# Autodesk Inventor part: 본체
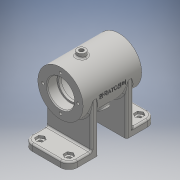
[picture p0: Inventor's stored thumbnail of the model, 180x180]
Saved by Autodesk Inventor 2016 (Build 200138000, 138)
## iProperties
Created: 2017-02
Part Number: 본체
Material: 일반
Document SubType Name: Modeling
Designer: USER
Density: 1 g/cm^3
Appearance: 기본값
Author: USER
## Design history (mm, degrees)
sketch "스케치1"
  geometry: L1 (0, 0)-(54, 0); L2 (54, 0)-(54, -35); L3 (54, -35)-(0, -35); L4 (0, -35)-(0, 0); L5 (0, -69)-(54, -69); L6 (54, -69)-(54, -104); L7 (54, -104)-(0, -104); L8 (0, -104)-(0, -69)
  constraints: 16 end point, 4 parallel, 2 horizontal, 2 perpendicular, 2 point on line
  dimensions: "d0" = 54 distance of L1.start L1.end; "d1" = 35 distance between parallel lines of L3 L1; "d3" = 104 distance between parallel lines of L7 L1; "d4" = 35 distance between parallel lines of L7 L5
extrude "돌출1" new body sketch "스케치1" distance "d5" = 8; taper "d6" = 0 deg
fillet "모깎기1" dims "d7" = 10
fillet "모깎기2" dims "d8" = 10
sketch "스케치2"
  geometry: L1 (0, -35)-(54, -35) reference; L2 (10, -4.804)-(14.5, -7.402); L3 (14.5, -7.402)-(14.5, -12.598); L4 (14.5, -12.598)-(10, -15.196); L5 (10, -15.196)-(5.5, -12.598); L6 (5.5, -12.598)-(5.5, -7.402); L7 (5.5, -7.402)-(10, -4.804); L8 (44, -4.804)-(48.5, -7.402); L9 (48.5, -7.402)-(48.5, -12.598); L10 (48.5, -12.598)-(44, -15.196); L11 (44, -15.196)-(39.5, -12.598); L12 (39.5, -12.598)-(39.5, -7.402); L13 (39.5, -7.402)-(44, -4.804); L14 (0, -10)-(0, -35) reference; L15 (54, -35)-(54, -10) reference; L16 (44, 0)-(10, 0) reference; C1 r 4.5 at (10, -10); C2 r 4.5 at (44, -10); A1 r 10 centre (10, -10) between (10, 0) and (0, -10) reference; A2 r 10 centre (44, -10) between (54, -10) and (44, 0) reference; 5 further points
  constraints: 24 end point, 2 centre point, 2 coincident, 2 midpoint, 2 tangent, 26 other
  dimensions: "d12" = 9 diameter of C1; "d13" = 9 diameter of C2
extrude "돌출2" cut sketch "스케치2" distance "d14" = 3; taper "d15" = 0 deg
sketch "스케치3"
  geometry: L1 (54, -69)-(0, -69) reference; L2 (10, -88.804)-(14.5, -91.402); L3 (14.5, -91.402)-(14.5, -96.598); L4 (14.5, -96.598)-(10, -99.196); L5 (10, -99.196)-(5.5, -96.598); L6 (5.5, -96.598)-(5.5, -91.402); L7 (5.5, -91.402)-(10, -88.804); L8 (44, -88.804)-(48.5, -91.402); L9 (48.5, -91.402)-(48.5, -96.598); L10 (48.5, -96.598)-(44, -99.196); L11 (44, -99.196)-(39.5, -96.598); L12 (39.5, -96.598)-(39.5, -91.402); L13 (39.5, -91.402)-(44, -88.804); L14 (54, -94)-(54, -69) reference; L15 (0, -69)-(0, -94) reference; L16 (10, -104)-(44, -104) reference; C1 r 4.5 at (10, -94); C2 r 4.5 at (44, -94); A1 r 10 centre (44, -94) between (44, -104) and (54, -94) reference; A2 r 10 centre (10, -94) between (0, -94) and (10, -104) reference; 5 further points
  constraints: 24 end point, 2 centre point, 2 coincident, 2 midpoint, 2 tangent, 26 other
  dimensions: "d16" = 9 diameter of C1; "d17" = 9 diameter of C2
extrude "돌출3" cut sketch "스케치3" distance "d18" = 3; taper "d19" = 0 deg
sketch "스케치4"
  geometry: L1 (-44, -104)-(-10, -104) reference; L2 (0, -94)-(0, -69) reference; L3 (0, -69)-(-54, -69) reference; L4 (-54, -69)-(-54, -94) reference; C1 r 2.5 at (-10, -94); C2 r 2.5 at (-44, -94); A1 r 10 centre (-44, -94) between (-54, -94) and (-44, -104) reference; A2 r 10 centre (-10, -94) between (-10, -104) and (0, -94) reference; 1 further point
  constraints: 2 centre point, 2 coincident
  dimensions: "d20" = 5 diameter of C1; "d21" = 5 diameter of C2
extrude "돌출4" cut sketch "스케치4" stored distance "d22" = 3; taper "d23" = 0 deg
sketch "스케치5"
  geometry: L1 (-10, 0)-(-44, 0) reference; L2 (-54, -10)-(-54, -35) reference; L3 (-54, -35)-(0, -35) reference; L4 (0, -35)-(0, -10) reference; C1 r 2.5 at (-10, -10); C2 r 2.5 at (-44, -10); A1 r 10 centre (-10, -10) between (0, -10) and (-10, 0) reference; A2 r 10 centre (-44, -10) between (-44, 0) and (-54, -10) reference; 1 further point
  constraints: 2 centre point, 2 coincident
  dimensions: "d24" = 5 diameter of C1; "d25" = 5 diameter of C2
extrude "돌출5" cut sketch "스케치5" stored distance "d26" = 3; taper "d27" = 0 deg
node "작업 평면1"
sketch "스케치6"
  geometry: L1 (54, 0)-(0, 0) reference; C1 r 27 at (27, 60); 1 further point
  constraints: 1 centre point, 1 midpoint, 1 vertical alignment
  dimensions: "d28" = 54 diameter of C1; "d29" = 60 distance from line of L1 C1.centre
extrude "돌출6" join sketch "스케치6" stored distance "d30" = 70; taper "d31" = 0 deg
sketch "스케치7"
  geometry: C1 r 27 at (0, 0) reference; C2 r 16 at (0, 0); 1 further point
  constraints: 1 centre point, 1 coincident
  dimensions: "d32" = 32 diameter of C2
extrude "돌출7" cut sketch "스케치7" distance "d33" = 12; taper "d34" = 0 deg
sketch "스케치8"
  geometry: C1 r 16 at (0, 0) reference; C2 r 14 at (0, 0); 1 further point
  constraints: 1 centre point, 1 coincident
  dimensions: "d35" = 28 diameter of C2
extrude "돌출8" cut sketch "스케치8" distance "d36" = 3; taper "d37" = 0 deg
fillet "모깎기4" dims "d38" = 0.3
chamfer "모따기1" distance "d39" = 1; stored, may be unused: second distance "d40" = 2, angle "d41" = 45 deg
sketch "스케치9"
  geometry: C1 r 14 at (0, 0) reference; C2 r 22 at (0, 0); 1 further point
  constraints: 1 centre point, 1 coincident
  dimensions: "d42" = 44 diameter of C2
extrude "돌출9" cut sketch "스케치9" distance "d43" = 40; taper "d44" = 0 deg
fillet "모깎기5" dims "d45" = 3
sketch "스케치10"
  geometry: C1 r 27 at (0, 0) reference; C2 r 16 at (0, 0); 1 further point
  constraints: 1 centre point, 1 coincident
  dimensions: "d46" = 32 diameter of C2
extrude "돌출10" cut sketch "스케치10" distance "d47" = 12; taper "d48" = 0 deg
chamfer "모따기2" distance "d49" = 1; stored, may be unused: second distance "d50" = 2, angle "d51" = 45 deg
fillet "모깎기6" dims "d52" = 0.3
sketch "스케치11"
  geometry: C1 r 15.7 at (0, 0) reference; C2 r 14 at (0, 0); 1 further point
  constraints: 1 centre point, 1 coincident
  dimensions: "d53" = 28 diameter of C2
extrude "돌출11" cut sketch "스케치11" distance "d54" = 3; taper "d55" = 0 deg
sketch "스케치12"
  geometry: L1 (0, -69)-(54, -69) reference; L2 (0, -69)-(54, -69); L3 (54, -69)-(54, -77); L4 (54, -77)-(0, -77); L5 (0, -77)-(0, -69); L6 (54, -35)-(0, -35) reference; L7 (0, -35)-(54, -35); L8 (54, -35)-(54, -27); L9 (54, -27)-(0, -27); L10 (0, -27)-(0, -35); 5 further points
  constraints: 16 end point, 4 midpoint, 4 parallel, 4 point on line, 2 horizontal, 2 perpendicular, 2 vertical alignment
  dimensions: "d56" = 8 distance of L4.end L2.start; "d57" = 8 distance of L9.end L7.start; "d58" = 54 distance between parallel lines of L3 L5
extrude "돌출12" join sketch "스케치12" stored distance "d59" = 3; taper "d60" = 0 deg
fillet "모깎기7" dims "d61" = 2
fillet "모깎기8" dims "d62" = 2
fillet "모깎기9" dims "d63" = 2
sketch "스케치13"
  geometry: C1 r 27 at (0, 0) reference; C2 r 17 at (0, 0) reference; A1 r 21 centre (0, 0) between (0, 21) and (-21, 0); 3 further points
  constraints: 4 point on circle, 2 horizontal alignment, 2 vertical alignment, 1 centre point, 1 coincident
  dimensions: "d64" = 42 diameter of A1
hole "구멍1" sketch "스케치13" at (0, 21), (-21, 0), (0, -21), (21, 0) diameter "d65" = 3.242; stored, may be unused: countersink angle "d69" = 90 deg, drill point angle "d71" = 118 deg; dims "d66" = 8, "d67" = 4, "d68" = 2, "d70" = 10
node "작업 평면3"
sketch "스케치14"
  geometry: L1 (-17, -52)-(17, -52) reference; L2 (-27, -35)-(27, -35) reference; C1 r 5 at (0, -10); 2 further points
  constraints: 1 centre point, 1 midpoint, 1 vertical alignment
  dimensions: "d73" = 10 diameter of C1; "d74" = 25 distance from line of L2 C1.centre
extrude "돌출13" join sketch "스케치14" stored distance "d75" = 3; taper "d76" = 0 deg
fillet "모깎기10" dims "d77" = 2
sketch "스케치18"
  geometry: C1 r 5 at (0, 0) reference; 1 further point
  constraints: 1 coincident
hole "구멍3" sketch "스케치18" at (0, 0) diameter "d85" = 5.188; stored, may be unused: countersink angle "d89" = 90 deg, drill point angle "d91" = 0 deg; dims "d86" = 12, "d87" = 4, "d88" = 2, "d90" = 16
node "작업 평면5"
sketch "스케치20"
  geometry: L1 (0, 0)-(16.339, -25.16); L2 (0, 0)-(0, -14); 2 further points
  constraints: 4 end point, 1 coincident, 1 vertical, 1 vertical alignment, 1 other
  dimensions: "d92" = 30 distance of L1.start L1.end; "d93" = 33 deg angle of L2 L1
node "작업 평면6"
sketch "스케치21"
  geometry: C1 r 6 at (0, 0); 2 further points
  constraints: 1 centre point, 1 coincident
  dimensions: "d94" = 12 diameter of C1
extrude "돌출14" join sketch "스케치21" stored distance "d95" = 3; taper "d96" = 0 deg
fillet "모깎기11" dims "d97" = 2
sketch "스케치22"
  geometry: C1 r 6 at (0, 0) reference; 2 further points
  constraints: 1 coincident
hole "구멍4" sketch "스케치22" at (0, 0) diameter "d98" = 5.188; stored, may be unused: countersink angle "d102" = 90 deg, drill point angle "d104" = 0 deg; dims "d99" = 12, "d100" = 4, "d101" = 2, "d103" = 16
node "작업 평면7"
sketch "스케치23"
  geometry: L1 (23, 0)-(19, 0) reference; L2 (35, 27)-(-35, 27) reference; L3 (-35, 27)-(-35, -27) reference; 4 further points
  constraints: 1 midpoint, 1 other
  dimensions: "d105" = 27 distance from line of L2 point (0, 0); "d106" = 35 distance from line of L3 point (0, 0)
feature "엠보싱1" sketch "스케치23" dims "d107" = 0.5, "d108" = 0
node "솔리드1"
mirror "대칭1"
node "투영된 루프1"
node "투영된 루프2"
node "투영된 루프3"
node "투영된 루프4"
node "투영된 루프5"
node "투영된 루프6"
node "투영된 루프7"
node "투영된 루프8"
node "투영된 루프9"
node "투영된 루프10"
node "투영된 루프12"
node "투영된 루프13"
